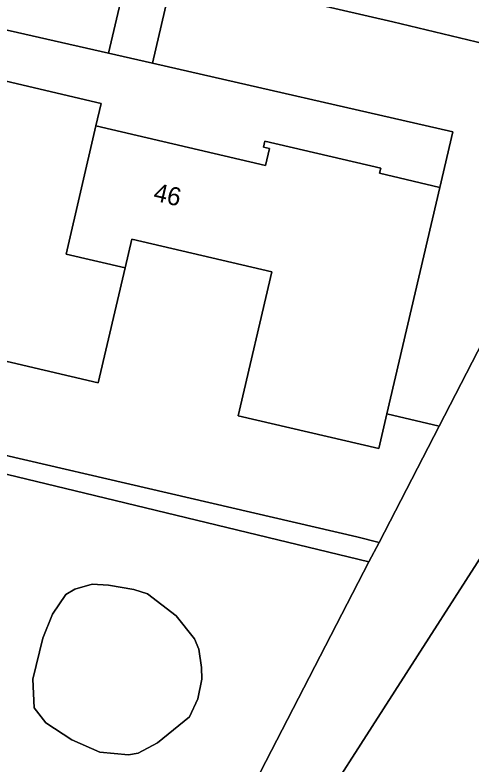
# Model space of a CAD drawing. Extents: x 162184 to 163154, y 385507 to 386516.
# Drawn here: x 162587.19 to 162612.3, y 385627.46 to 385668.7 of the extents above; entities that cross this region are included whole.
import ezdxf

# ---------------------------------------------------------------- set-up
doc = ezdxf.new("R2010")
doc.units = 0
for name, color, linetype in [('IMGEO_Erf', 7, 'Continuous'), ('IMGEO_Grasland_overig', 7, 'Continuous'), ('IMGEO_Groenvoorziening', 7, 'Continuous'), ('IMGEO_Muur', 7, 'Continuous'), ('IMGEO_Pand', 7, 'Continuous'), ('IMGEO_Pand_nummerreeks', 7, 'Continuous'), ('IMGEO_Rijbaan_lokaal_gesloten', 7, 'Continuous'), ('IMGEO_Voetpad_open', 7, 'Continuous')]:
    doc.layers.add(name, color=color, linetype=linetype)

msp = doc.modelspace()

# ---------------------------------------------------------------- linework, layer by layer
at = {"layer": 'IMGEO_Erf'}
msp.add_lwpolyline([(162585.45, 385665.351), (162591.937, 385663.833), (162591.646, 385662.588), (162600.977, 385660.405), (162601.197, 385661.343), (162600.875, 385661.418), (162600.952, 385661.747), (162607.333, 385660.255), (162607.269, 385659.983), (162610.585, 385659.207), (162611.301, 385662.267), (162594.761, 385666.037), (162592.348, 385666.587), (162581.743, 385669.004)], dxfattribs=at)
msp.add_lwpolyline([(162601.336, 385654.555), (162593.627, 385656.359), (162593.256, 385654.774), (162591.777, 385648.451), (162584.008, 385650.269), (162585.855, 385658.163), (162578.156, 385659.964), (162577.788, 385658.393), (162575.152, 385647.123), (162606.008, 385639.975), (162607.236, 385639.664), (162610.543, 385646.068), (162607.668, 385646.74), (162607.22, 385644.823), (162599.483, 385646.633)], close=True, dxfattribs=at)
at = {"layer": 'IMGEO_Grasland_overig'}
msp.add_lwpolyline([(162616.707, 385666.223), (162607.987, 385668.312), (162595.943, 385671.116), (162594.761, 385666.037), (162611.301, 385662.267), (162610.585, 385659.207), (162607.668, 385646.74), (162610.543, 385646.068), (162618.713, 385661.89)], dxfattribs=at)
at = {"layer": 'IMGEO_Groenvoorziening'}
for points in [[(162593.532, 385671.677), (162582.915, 385674.148), (162581.743, 385669.004), (162592.348, 385666.587)], [(162588.25, 385630.554), (162588.183, 385632.142), (162588.723, 385634.391), (162589.266, 385635.714), (162589.988, 385636.795), (162590.482, 385637.089), (162591.434, 385637.358), (162592.335, 385637.309), (162593.745, 385637.071), (162594.482, 385636.832), (162596.059, 385635.616), (162597.078, 385634.361), (162597.321, 385633.778), (162597.463, 385632.775), (162597.477, 385632.127), (162597.263, 385631.059), (162596.809, 385630.067), (162595.047, 385628.628), (162593.982, 385628.066), (162593.449, 385627.963), (162591.874, 385628.112), (162590.323, 385628.794), (162588.899, 385629.73)], [(162593.449, 385627.963), (162593.982, 385628.066), (162595.047, 385628.628), (162596.809, 385630.067), (162597.263, 385631.059), (162597.477, 385632.127), (162597.463, 385632.775), (162597.321, 385633.778), (162597.078, 385634.361), (162596.059, 385635.616), (162594.482, 385636.832), (162593.745, 385637.071), (162592.335, 385637.309), (162591.434, 385637.358), (162590.482, 385637.089), (162589.988, 385636.795), (162589.266, 385635.714), (162588.723, 385634.391), (162588.183, 385632.142), (162588.25, 385630.554), (162588.899, 385629.73), (162590.323, 385628.794), (162591.874, 385628.112)]]:
    msp.add_lwpolyline(points, close=True, dxfattribs=at)
for points in [[(162580.904, 385644.813), (162591.033, 385642.365), (162606.679, 385638.585), (162607.236, 385639.664), (162606.008, 385639.975), (162575.152, 385647.123)], [(162551.663, 385645.322), (162592.871, 385618.869), (162593.412, 385618.564), (162593.678, 385618.488), (162593.95, 385618.436), (162594.225, 385618.409), (162594.502, 385618.407), (162594.777, 385618.429), (162595.05, 385618.475), (162595.317, 385618.546), (162595.577, 385618.641), (162595.828, 385618.758), (162596.067, 385618.897), (162596.292, 385619.057), (162596.503, 385619.237), (162596.696, 385619.434), (162596.872, 385619.648), (162597.027, 385619.877), (162597.072, 385619.953), (162600.421, 385626.466), (162606.679, 385638.585), (162591.033, 385642.365), (162580.904, 385644.813)]]:
    msp.add_lwpolyline(points, dxfattribs=at)
at = {"layer": 'IMGEO_Muur'}
msp.add_lwpolyline([(162610.543, 385646.068), (162607.669, 385646.74)], dxfattribs=at)
at = {"layer": 'IMGEO_Pand'}
for points in [[(162590.008, 385655.534), (162591.646, 385662.588), (162591.937, 385663.833), (162585.45, 385665.351), (162585.375, 385665.031), (162585.704, 385664.954), (162585.478, 385663.987), (162576.142, 385666.171), (162574.495, 385659.164), (162577.788, 385658.393), (162578.156, 385659.964), (162585.855, 385658.163), (162584.008, 385650.269), (162591.777, 385648.451), (162593.256, 385654.774)], [(162610.585, 385659.207), (162607.269, 385659.983), (162607.333, 385660.255), (162600.952, 385661.747), (162600.875, 385661.418), (162601.197, 385661.343), (162600.977, 385660.405), (162591.646, 385662.588), (162590.008, 385655.534), (162593.256, 385654.774), (162593.627, 385656.359), (162601.336, 385654.555), (162599.483, 385646.633), (162607.22, 385644.823), (162607.668, 385646.74)]]:
    msp.add_lwpolyline(points, close=True, dxfattribs=at)
at = {"layer": 'IMGEO_Rijbaan_lokaal_gesloten'}
msp.add_lwpolyline([(162633.464, 385678.05), (162624.375, 385660.767), (162623.422, 385658.984), (162613.514, 385639.963), (162613.495, 385639.909), (162613.431, 385639.771), (162613.355, 385639.64), (162613.268, 385639.516), (162602.94, 385623.427)], dxfattribs=at)
at = {"layer": 'IMGEO_Voetpad_open'}
msp.add_lwpolyline([(162595.943, 385671.116), (162593.532, 385671.677), (162592.348, 385666.587), (162594.761, 385666.037)], close=True, dxfattribs=at)
for points in [[(162595.943, 385671.116), (162607.987, 385668.312), (162616.707, 385666.223)], [(162618.713, 385661.89), (162610.543, 385646.068), (162607.236, 385639.664), (162606.679, 385638.585), (162600.421, 385626.466)], [(162602.94, 385623.427), (162613.268, 385639.516)]]:
    msp.add_lwpolyline(points, dxfattribs=at)

# ---------------------------------------------------------------- texts
at = {"layer": 'IMGEO_Pand_nummerreeks'}
msp.add_text('46', height=1, rotation=346.8334, dxfattribs=at).set_placement((162594.76, 385658.491))

doc.saveas('drawing.dxf')
